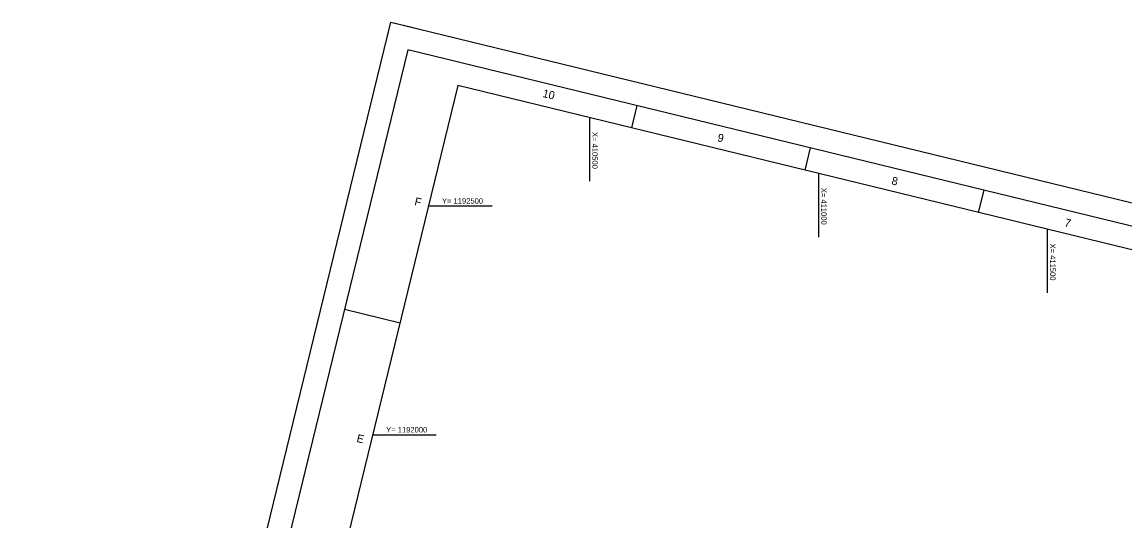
# Model space of a CAD drawing. Extents: x 409260 to 414340, y 1188556 to 1192902.
# Drawn here: x 409260 to 411669, y 1191812 to 1192902 of the extents above; entities that cross this region are included whole.
import ezdxf

# ---------------------------------------------------------------- set-up
doc = ezdxf.new("R2010")
doc.units = 0
for name, color, linetype in [('G-ANNO-NPLT', 7, 'Continuous'), ('G-ANNO-TTLB', 7, 'Continuous'), ('V-TOPO-COOR-STAT', 7, 'Continuous')]:
    doc.layers.add(name, color=color, linetype=linetype)

msp = doc.modelspace()

# ---------------------------------------------------------------- linework, layer by layer
at = {"layer": 'G-ANNO-NPLT'}
msp.add_lwpolyline([(410065.6, 1192901.9), (414340.3, 1191859.4), (413534.7, 1188556.2), (409260, 1189598.7)], close=True, dxfattribs=at)
msp.add_lwpolyline([(410053.7, 1192853.3), (410065.6, 1192901.9), (410114.2, 1192890)], dxfattribs=at)
at = {"layer": 'G-ANNO-TTLB'}
for p, q in [((410602.6, 1192719.4), (410590.8, 1192670.9)), ((410981.5, 1192627), (410969.7, 1192578.5)), ((410981.5, 1192627), (410969.7, 1192578.5)), ((411360.4, 1192534.6), (411348.6, 1192486)), ((409964.1, 1192274.6), (410085.5, 1192244.9))]:
    msp.add_line(p, q, dxfattribs=at)
for points in [[(409320.4, 1189635.4), (413498, 1188616.6), (414279.8, 1191822.7), (410102.3, 1192841.4)], [(414219.4, 1191785.9), (410211.9, 1192763.3), (409453.7, 1189654.4), (413461.3, 1188677.1)]]:
    msp.add_lwpolyline(points, close=True, dxfattribs=at)
at = {"layer": 'V-TOPO-COOR-STAT'}
for p, q in [((410500, 1192553.8), (410500, 1192692.7)), ((411000, 1192431.9), (411000, 1192570.8)), ((410147.7, 1192500), (410286.7, 1192500)), ((411500, 1192309.9), (411500, 1192448.9)), ((410025.8, 1192000), (410164.7, 1192000))]:
    msp.add_line(p, q, dxfattribs=at)

# ---------------------------------------------------------------- texts
at = {"layer": 'G-ANNO-TTLB'}
for s, p in [('10', (410395.8, 1192738.4)), ('9', (410777.6, 1192641.7)), ('8', (411157.8, 1192547.3)), ('F', (410115.9, 1192502.2)), ('7', (411535.6, 1192455.9)), ('E', (409989.5, 1191984.7))]:
    msp.add_text(s, height=17.5, rotation=346.2946, dxfattribs=at).set_placement(p)
at = {"layer": 'V-TOPO-COOR-STAT'}
for s, p in [('X= 410500', (410505.3, 1192661.6)), ('X= 411000', (411005.3, 1192539.6)), ('X= 411500', (411505.3, 1192417.7))]:
    msp.add_text(s, height=12, rotation=270, dxfattribs=at).set_placement(p)
for s, p in [('Y= 1192500', (410177.1, 1192505)), ('Y= 1192000', (410055.2, 1192005))]:
    msp.add_text(s, height=12, dxfattribs=at).set_placement(p)

doc.saveas('drawing.dxf')
